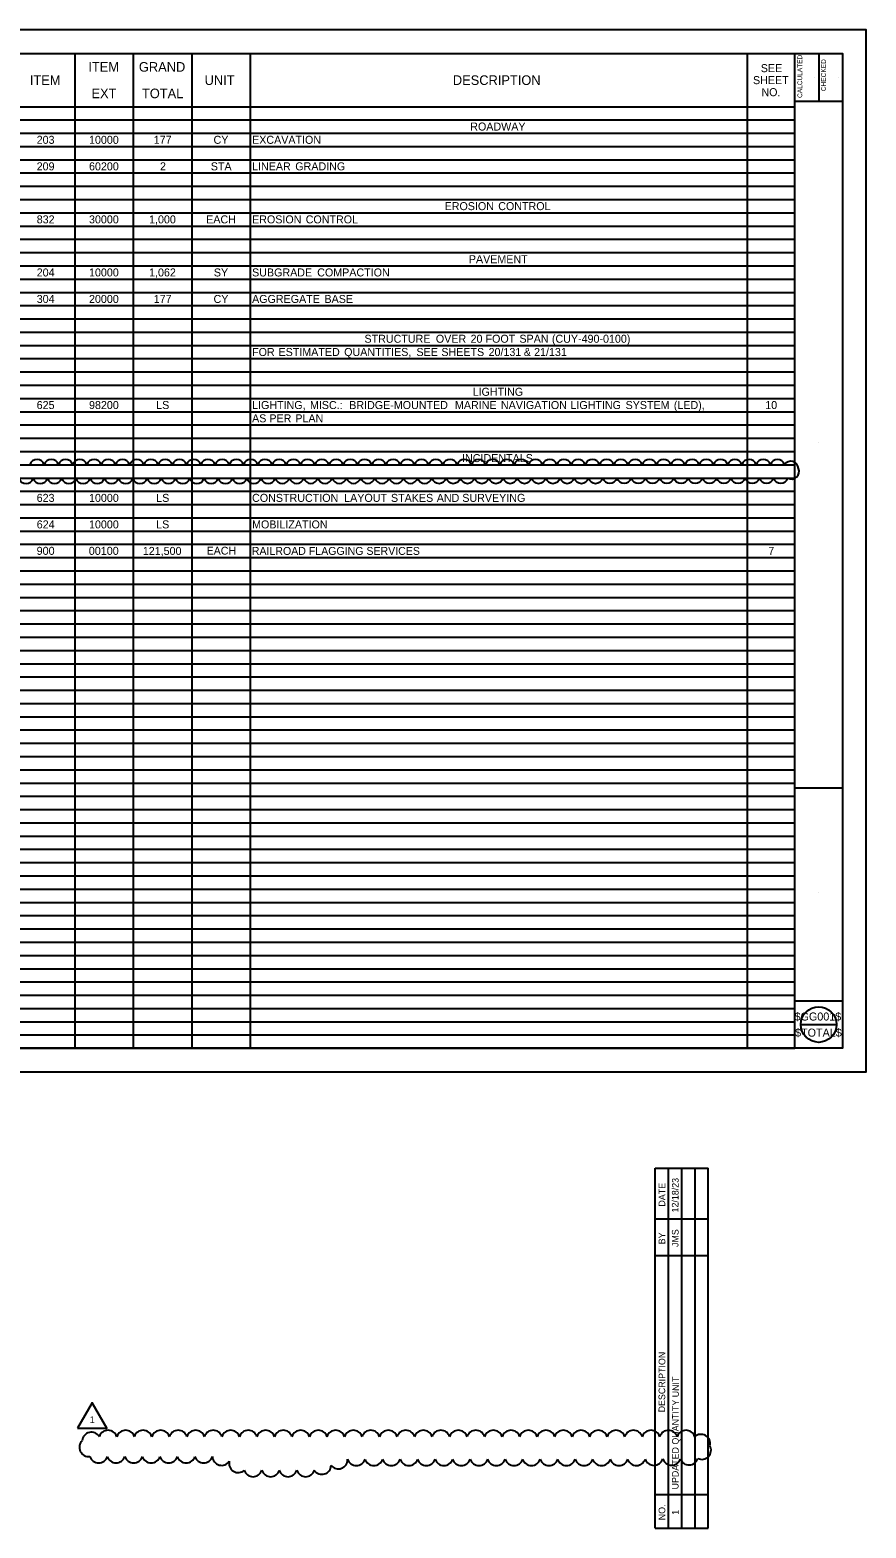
# Model space of a CAD drawing. Extents: x 0 to 34, y -9.6 to 22.
# Drawn here: x 16.35 to 34, y -9.63 to 22 of the extents above; entities that cross this region are included whole.
import ezdxf

# ---------------------------------------------------------------- set-up
doc = ezdxf.new("R2010")
doc.units = 0
for name, color, linetype in [('Default', 7, 'Continuous'), ('MU_Markup_Cloud', 7, 'Continuous'), ('MU_Markup_Text', 7, 'Continuous'), ('SH_Border', 7, 'Continuous'), ('SH_Cut_Line', 7, 'Continuous'), ('SH_Data', 7, 'Continuous'), ('SH_Text', 7, 'Continuous')]:
    doc.layers.add(name, color=color, linetype=linetype)

msp = doc.modelspace()

# ---------------------------------------------------------------- linework, layer by layer
at = {"layer": 'Default'}
for p, q in [((15.06, 21.5), (17.299, 21.5)), ((17.299, 21.5), (19.77, 21.5)), ((17.299, 0.5), (17.299, 21.5)), ((18.535, 0.5), (18.535, 21.5)), ((19.77, 21.5), (21.005, 21.5)), ((19.77, 0.5), (19.77, 21.5)), ((21.005, 21.5), (31.495, 21.5)), ((21.005, 0.5), (21.005, 21.5)), ((31.495, 21.5), (32.5, 21.5)), ((31.495, 0.5), (31.495, 21.5)), ((32.5, 0.5), (32.5, 21.5)), ((14.055, 20.38), (32.5, 20.38)), ((19.77, 20.38), (32.5, 20.38)), ((2, 20.1), (32.5, 20.1)), ((2, 19.82), (32.5, 19.82)), ((2, 19.54), (32.5, 19.54)), ((2, 19.26), (32.5, 19.26)), ((2, 18.98), (32.5, 18.98)), ((2, 18.7), (32.5, 18.7)), ((2, 18.42), (32.5, 18.42)), ((2, 18.14), (32.5, 18.14)), ((2, 17.86), (32.5, 17.86)), ((2, 17.58), (32.5, 17.58)), ((2, 17.3), (32.5, 17.3)), ((2, 17.02), (32.5, 17.02)), ((2, 16.74), (32.5, 16.74)), ((2, 16.46), (32.5, 16.46)), ((2, 16.18), (32.5, 16.18)), ((2, 15.9), (32.5, 15.9)), ((2, 15.62), (32.5, 15.62)), ((2, 15.34), (32.5, 15.34)), ((2, 15.06), (32.5, 15.06)), ((2, 14.78), (32.5, 14.78)), ((2, 14.5), (32.5, 14.5)), ((2, 14.22), (32.5, 14.22)), ((2, 13.94), (32.5, 13.94)), ((2, 13.66), (32.5, 13.66)), ((2, 13.38), (32.5, 13.38)), ((2, 13.1), (32.5, 13.1)), ((2, 12.82), (32.5, 12.82)), ((2, 12.54), (32.5, 12.54)), ((2, 12.26), (32.5, 12.26)), ((2, 11.98), (32.5, 11.98)), ((2, 11.7), (32.5, 11.7)), ((2, 11.42), (32.5, 11.42)), ((2, 11.14), (32.5, 11.14)), ((2, 10.86), (32.5, 10.86)), ((2, 10.58), (32.5, 10.58)), ((2, 10.3), (32.5, 10.3)), ((2, 10.02), (32.5, 10.02)), ((2, 9.74), (32.5, 9.74)), ((2, 9.46), (32.5, 9.46)), ((2, 9.18), (32.5, 9.18)), ((2, 8.9), (32.5, 8.9)), ((2, 8.62), (32.5, 8.62)), ((2, 8.34), (32.5, 8.34)), ((2, 8.06), (32.5, 8.06)), ((2, 7.78), (32.5, 7.78)), ((2, 7.5), (32.5, 7.5)), ((2, 7.22), (32.5, 7.22)), ((2, 6.94), (32.5, 6.94)), ((2, 6.66), (32.5, 6.66)), ((2, 6.38), (32.5, 6.38)), ((2, 6.1), (32.5, 6.1)), ((2, 5.82), (32.5, 5.82)), ((2, 5.54), (32.5, 5.54)), ((2, 5.26), (32.5, 5.26)), ((2, 4.98), (32.5, 4.98)), ((2, 4.7), (32.5, 4.7)), ((2, 4.42), (32.5, 4.42)), ((2, 4.14), (32.5, 4.14)), ((2, 3.86), (32.5, 3.86)), ((2, 3.58), (32.5, 3.58)), ((2, 3.3), (32.5, 3.3)), ((2, 3.02), (32.5, 3.02)), ((2, 2.74), (32.5, 2.74)), ((2, 2.46), (32.5, 2.46)), ((2, 2.18), (32.5, 2.18)), ((2, 1.9), (32.5, 1.9)), ((2, 1.62), (32.5, 1.62)), ((2, 1.34), (32.5, 1.34)), ((2, 1.06), (32.5, 1.06)), ((2, 0.78), (32.5, 0.78)), ((2, 0.5), (32.5, 0.5))]:
    msp.add_line(p, q, dxfattribs=at)
at = {"layer": 'MU_Markup_Cloud'}
msp.add_lwpolyline([(17.351, -7.521), (17.97, -7.521), (17.661, -6.985)], close=True, dxfattribs=at)
for centre, radius, start, end in [((16.498, 12.773), 0.158, 17.5, 162.5), ((16.799, 12.773), 0.158, 17.5, 162.5), ((17.1, 12.773), 0.158, 17.5, 162.5), ((17.4, 12.773), 0.158, 17.5, 162.5), ((17.701, 12.773), 0.158, 17.5, 162.5), ((18.002, 12.773), 0.158, 17.5, 162.5), ((18.302, 12.773), 0.158, 17.5, 162.5), ((18.603, 12.773), 0.158, 17.5, 162.5), ((18.903, 12.773), 0.158, 17.5, 162.5), ((19.204, 12.773), 0.158, 17.5, 162.5), ((19.505, 12.773), 0.158, 17.5, 162.5), ((19.805, 12.773), 0.158, 17.5, 162.5), ((20.106, 12.773), 0.158, 17.5, 162.5), ((20.407, 12.773), 0.158, 17.5, 162.5), ((20.707, 12.773), 0.158, 17.5, 162.5), ((21.008, 12.773), 0.158, 17.5, 162.5), ((21.309, 12.773), 0.158, 17.5, 162.5), ((21.609, 12.773), 0.158, 17.5, 162.5), ((21.91, 12.773), 0.158, 17.5, 162.5), ((22.21, 12.773), 0.158, 17.5, 162.5), ((22.511, 12.773), 0.158, 17.5, 162.5), ((22.812, 12.773), 0.158, 17.5, 162.5), ((23.112, 12.773), 0.158, 17.5, 162.5), ((23.413, 12.773), 0.158, 17.5, 162.5), ((23.714, 12.773), 0.158, 17.5, 162.5), ((24.014, 12.773), 0.158, 17.5, 162.5), ((24.315, 12.773), 0.158, 17.5, 162.5), ((24.615, 12.773), 0.158, 17.5, 162.5), ((24.916, 12.773), 0.158, 17.5, 162.5), ((25.217, 12.773), 0.158, 17.5, 162.5), ((25.517, 12.773), 0.158, 17.5, 162.5), ((25.818, 12.773), 0.158, 17.5, 162.5), ((26.119, 12.773), 0.158, 17.5, 162.5), ((26.419, 12.773), 0.158, 17.5, 162.5), ((26.72, 12.773), 0.158, 17.5, 162.5), ((27.021, 12.773), 0.158, 17.5, 162.5), ((27.321, 12.773), 0.158, 17.5, 162.5), ((27.622, 12.773), 0.158, 17.5, 162.5), ((27.922, 12.773), 0.158, 17.5, 162.5), ((28.223, 12.773), 0.158, 17.5, 162.5), ((28.524, 12.773), 0.158, 17.5, 162.5), ((28.824, 12.773), 0.158, 17.5, 162.5), ((29.125, 12.773), 0.158, 17.5, 162.5), ((29.426, 12.773), 0.158, 17.5, 162.5), ((29.726, 12.773), 0.158, 17.5, 162.5), ((30.027, 12.773), 0.158, 17.5, 162.5), ((30.327, 12.773), 0.158, 17.5, 162.5), ((30.628, 12.773), 0.158, 17.5, 162.5), ((30.929, 12.773), 0.158, 17.5, 162.5), ((31.229, 12.773), 0.158, 17.5, 162.5), ((31.53, 12.773), 0.158, 17.5, 162.5), ((31.831, 12.773), 0.158, 17.5, 162.5), ((32.131, 12.773), 0.158, 17.5, 162.5), ((32.414, 12.735), 0.158, 2.1746, 147.1746), ((32.429, 12.674), 0.157, 239.8312, 24.8312), ((16.266, 12.582), 0.158, 197.5195, 342.5195), ((16.566, 12.582), 0.158, 197.5197, 342.5197), ((16.867, 12.582), 0.158, 197.5199, 342.5199), ((17.168, 12.582), 0.158, 197.5201, 342.5201), ((17.468, 12.582), 0.158, 197.5201, 342.5201), ((17.769, 12.582), 0.158, 197.52, 342.52), ((18.069, 12.582), 0.158, 197.5199, 342.5199), ((18.37, 12.582), 0.158, 197.5198, 342.5198), ((18.671, 12.583), 0.158, 197.5198, 342.5198), ((18.971, 12.583), 0.158, 197.5197, 342.5197), ((19.272, 12.583), 0.158, 197.5196, 342.5196), ((19.573, 12.583), 0.158, 197.5195, 342.5195), ((19.873, 12.583), 0.158, 197.5194, 342.5194), ((20.174, 12.583), 0.158, 197.5193, 342.5193), ((20.474, 12.583), 0.158, 197.5192, 342.5192), ((20.775, 12.583), 0.158, 197.519, 342.519), ((21.076, 12.583), 0.158, 197.5189, 342.5189), ((21.376, 12.583), 0.158, 197.5188, 342.5188), ((21.677, 12.584), 0.158, 197.5187, 342.5187), ((21.978, 12.584), 0.158, 197.5185, 342.5185), ((22.278, 12.584), 0.158, 197.5184, 342.5184), ((22.579, 12.584), 0.158, 197.5182, 342.5182), ((22.88, 12.584), 0.158, 197.5181, 342.5181), ((23.18, 12.584), 0.158, 197.5179, 342.5179), ((23.481, 12.584), 0.158, 197.5178, 342.5178), ((23.781, 12.584), 0.158, 197.5176, 342.5176), ((24.082, 12.584), 0.158, 197.5174, 342.5174), ((24.383, 12.584), 0.158, 197.5172, 342.5172), ((24.683, 12.584), 0.158, 197.517, 342.517), ((24.984, 12.585), 0.158, 197.5168, 342.5168), ((25.285, 12.585), 0.158, 197.5166, 342.5166), ((25.585, 12.585), 0.158, 197.5163, 342.5163), ((25.886, 12.585), 0.158, 197.516, 342.516), ((26.186, 12.585), 0.158, 197.5158, 342.5158), ((26.487, 12.585), 0.158, 197.5155, 342.5155), ((26.788, 12.585), 0.158, 197.5151, 342.5151), ((27.088, 12.585), 0.158, 197.5148, 342.5148), ((27.389, 12.585), 0.158, 197.5144, 342.5144), ((27.69, 12.585), 0.158, 197.514, 342.514), ((27.99, 12.585), 0.158, 197.5135, 342.5135), ((28.291, 12.585), 0.158, 197.513, 342.513), ((28.592, 12.586), 0.158, 197.5124, 342.5124), ((28.892, 12.586), 0.158, 197.5118, 342.5118), ((29.193, 12.586), 0.158, 197.5111, 342.5111), ((29.493, 12.586), 0.158, 197.5102, 342.5102), ((29.794, 12.586), 0.158, 197.5093, 342.5093), ((30.095, 12.586), 0.158, 197.5081, 342.5081), ((30.395, 12.586), 0.158, 197.5067, 342.5067), ((30.696, 12.586), 0.158, 197.505, 342.505), ((30.997, 12.586), 0.158, 197.5028, 342.5028), ((31.297, 12.586), 0.158, 197.4998, 342.4998), ((31.598, 12.586), 0.158, 197.4955, 342.4955), ((31.898, 12.586), 0.158, 197.488, 342.488), ((32.199, 12.586), 0.158, 197.4703, 342.4703), ((17.998, -7.76), 0.194, 17.5, 162.5), ((18.367, -7.76), 0.194, 17.5, 162.5), ((18.737, -7.76), 0.194, 17.5, 162.5), ((19.107, -7.76), 0.194, 17.5, 162.5), ((19.477, -7.76), 0.194, 17.5, 162.5), ((19.846, -7.76), 0.194, 17.5, 162.5), ((20.216, -7.76), 0.194, 17.5, 162.5), ((20.586, -7.76), 0.194, 17.5, 162.5), ((20.956, -7.76), 0.194, 17.5, 162.5), ((21.325, -7.76), 0.194, 17.5, 162.5), ((21.695, -7.76), 0.194, 17.5, 162.5), ((22.065, -7.76), 0.194, 17.5, 162.5), ((22.435, -7.76), 0.194, 17.5, 162.5), ((22.804, -7.76), 0.194, 17.5, 162.5), ((23.174, -7.76), 0.194, 17.5, 162.5), ((23.544, -7.76), 0.194, 17.5, 162.5), ((23.914, -7.76), 0.194, 17.5, 162.5), ((24.283, -7.76), 0.194, 17.5, 162.5), ((24.653, -7.76), 0.194, 17.5, 162.5), ((25.023, -7.76), 0.194, 17.5, 162.5), ((25.393, -7.76), 0.194, 17.5, 162.5), ((25.762, -7.76), 0.194, 17.5, 162.5), ((26.132, -7.76), 0.194, 17.5, 162.5), ((26.502, -7.76), 0.194, 17.5, 162.5), ((26.871, -7.76), 0.194, 17.5, 162.5), ((27.241, -7.76), 0.194, 17.5, 162.5), ((27.611, -7.76), 0.194, 17.5, 162.5), ((27.981, -7.76), 0.194, 17.5, 162.5), ((28.35, -7.76), 0.194, 17.5, 162.5), ((28.72, -7.76), 0.194, 17.5, 162.5), ((29.09, -7.76), 0.194, 17.5, 162.5), ((29.46, -7.76), 0.194, 17.5, 162.5), ((29.829, -7.76), 0.194, 17.5, 162.5), ((30.199, -7.76), 0.194, 17.5, 162.5), ((17.585, -7.927), 0.194, 133.161, 278.161), ((17.646, -7.8), 0.194, 30.5448, 175.5448), ((30.513, -7.846), 0.194, 346.6844, 131.6844), ((30.533, -7.986), 0.194, 244.2994, 29.2994), ((17.797, -8.06), 0.194, 197.5, 342.5), ((18.167, -8.06), 0.194, 197.5, 342.5), ((18.537, -8.06), 0.194, 197.5, 342.5), ((18.907, -8.06), 0.194, 197.5, 342.5), ((19.276, -8.06), 0.194, 197.5, 342.5), ((19.646, -8.06), 0.194, 197.5, 342.5), ((20.016, -8.06), 0.194, 197.5, 342.5), ((20.395, -8.113), 0.194, 181.5215, 326.5215), ((20.745, -8.265), 0.194, 166.5598, 311.5598), ((22.86, -8.187), 0.194, 217.8482, 2.8482), ((23.238, -8.119), 0.194, 197.5, 342.5), ((23.608, -8.119), 0.194, 197.5, 342.5), ((23.978, -8.119), 0.194, 197.5, 342.5), ((24.348, -8.119), 0.194, 197.5, 342.5), ((24.718, -8.119), 0.194, 197.5, 342.5), ((25.087, -8.119), 0.194, 197.5, 342.5), ((25.457, -8.119), 0.194, 197.5, 342.5), ((25.827, -8.119), 0.194, 197.5, 342.5), ((26.196, -8.119), 0.194, 197.5, 342.5), ((26.566, -8.119), 0.194, 197.5, 342.5), ((26.936, -8.119), 0.194, 197.509, 342.509), ((27.306, -8.119), 0.194, 197.5309, 342.5309), ((27.675, -8.119), 0.194, 197.557, 342.557), ((28.045, -8.118), 0.194, 197.5885, 342.5885), ((28.415, -8.118), 0.194, 197.6278, 342.6278), ((28.784, -8.117), 0.194, 197.6786, 342.6786), ((29.154, -8.115), 0.194, 197.7481, 342.7481), ((29.524, -8.113), 0.194, 197.8514, 342.8514), ((29.893, -8.11), 0.194, 198.0307, 343.0307), ((30.263, -8.105), 0.194, 198.4927, 343.4927), ((21.058, -8.352), 0.194, 197.5, 342.5), ((21.428, -8.352), 0.194, 197.5, 342.5), ((21.798, -8.352), 0.194, 197.5, 342.5), ((22.167, -8.352), 0.194, 197.5, 342.5), ((22.513, -8.302), 0.194, 213.8846, 358.8846)]:
    msp.add_arc(centre, radius, start, end, dxfattribs=at)
at = {"layer": 'MU_Markup_Text'}
for p, q in [((29.549, -9.63), (29.549, -2.03)), ((29.549, -2.03), (30.669, -2.03)), ((29.829, -9.63), (29.829, -2.03)), ((30.109, -9.63), (30.109, -2.03)), ((30.389, -9.63), (30.389, -2.03)), ((30.669, -9.63), (30.669, -2.03)), ((29.549, -3.105), (30.669, -3.105)), ((29.549, -3.878), (30.669, -3.878)), ((29.549, -8.924), (30.669, -8.924)), ((29.549, -9.63), (30.669, -9.63))]:
    msp.add_line(p, q, dxfattribs=at)
at = {"layer": 'SH_Border'}
for p, q in [((32.5, 0.5), (32.5, 21.5)), ((33, 21.5), (33, 20.5)), ((32.5, 20.5), (33.5, 20.5)), ((32.5, 6), (33.5, 6)), ((32.5, 1.5), (33.5, 1.5))]:
    msp.add_line(p, q, dxfattribs=at)
msp.add_lwpolyline([(2, 21.5), (33.5, 21.5), (33.5, 0.5), (2, 0.5)], close=True, dxfattribs=at)
at = {"layer": 'SH_Cut_Line'}
msp.add_lwpolyline([(0, 0), (34, 0), (34, 22), (0, 22)], close=True, dxfattribs=at)
at = {"layer": 'SH_Data'}
for p, q in [((32.92, 21.004), (32.92, 21.004)), ((33.42, 21.004), (33.42, 21.004)), ((33, 13.292), (33, 13.292)), ((33, 3.792), (33, 3.792)), ((32.625, 1), (33.375, 1)), ((33, 1.085), (33, 1.085)), ((33, 0.745), (33, 0.745))]:
    msp.add_line(p, q, dxfattribs=at)
msp.add_circle((33, 1), 0.375, dxfattribs=at)

# ---------------------------------------------------------------- texts
at = {"layer": 'Default'}
for s, height, p in [('ITEM', 0.2027, (17.581, 21.119)), ('GRAND', 0.2027, (18.648, 21.119)), ('SEE', 0.1689, (31.778, 21.109)), ('ITEM', 0.2027, (16.345, 20.839)), ('UNIT', 0.2027, (20.036, 20.839)), ('DESCRIPTION', 0.20271, (25.277, 20.839)), ('SHEET', 0.1689, (31.613, 20.856)), ('EXT', 0.2027, (17.647, 20.559)), ('TOTAL', 0.2027, (18.713, 20.559)), ('NO.', 0.1689, (31.791, 20.602)), ('ROADWAY', 0.1689, (25.644, 19.876)), ('203', 0.1689, (16.49, 19.596)), ('10000', 0.1689, (17.595, 19.596)), ('177', 0.1689, (18.961, 19.596)), ('CY', 0.1689, (20.224, 19.596)), ('EXCAVATION', 0.1689, (21.038, 19.596)), ('209', 0.1689, (16.49, 19.036)), ('60200', 0.1689, (17.595, 19.036)), ('2', 0.169, (19.093, 19.036)), ('STA', 0.1689, (20.166, 19.036)), ('LINEAR', 0.1689, (21.038, 19.036)), (' GRADING', 0.1689, (21.887, 19.036)), ('EROSION', 0.1689, (25.103, 18.196)), (' CONTROL', 0.1689, (26.172, 18.196)), ('832', 0.1689, (16.491, 17.916)), ('30000', 0.1689, (17.595, 17.916)), ('1,000', 0.1689, (18.863, 17.916)), ('EACH', 0.1689, (20.069, 17.916)), ('EROSION', 0.1689, (21.038, 17.916)), (' CONTROL', 0.1689, (22.107, 17.916)), ('PAVEMENT', 0.1689, (25.614, 17.076)), ('204', 0.1689, (16.491, 16.796)), ('10000', 0.1689, (17.595, 16.796)), ('1,062', 0.1689, (18.863, 16.796)), ('SY', 0.1689, (20.231, 16.796)), ('SUBGRADE', 0.1689, (21.038, 16.796)), (' COMPACTION', 0.16893, (22.35, 16.796)), ('304', 0.1689, (16.491, 16.236)), ('20000', 0.1689, (17.595, 16.236)), ('177', 0.1689, (18.961, 16.236)), ('CY', 0.1689, (20.224, 16.236)), ('AGGREGATE', 0.1689, (21.038, 16.236)), (' BASE', 0.1689, (22.503, 16.236)), ('STRUCTURE', 0.1689, (23.411, 15.396)), (' OVER', 0.1689, (24.855, 15.396)), (' 20', 0.1689, (25.588, 15.396)), (' FOOT', 0.1689, (25.904, 15.396)), (' SPAN', 0.1689, (26.62, 15.396)), (' (CUY-490-0100)', 0.16893, (27.305, 15.396)), ('FOR', 0.1689, (21.038, 15.116)), (' ESTIMATED', 0.1689, (21.533, 15.116)), (' QUANTITIES,', 0.16893, (22.919, 15.116)), (' SEE', 0.1689, (24.445, 15.116)), (' SHEETS', 0.1689, (24.971, 15.116)), (' 20/131', 0.1689, (25.968, 15.116)), (' &', 0.1689, (26.712, 15.116)), (' 21/131', 0.1689, (26.929, 15.116)), ('LIGHTING', 0.1689, (25.694, 14.276)), ('625', 0.1689, (16.49, 13.996)), ('98200', 0.1689, (17.595, 13.996)), ('LS', 0.1689, (19.014, 13.996)), ('LIGHTING,', 0.1689, (21.038, 13.996)), (' MISC.:', 0.1689, (22.197, 13.996)), ('  BRIDGE-MOUNTED', 0.16893, (22.963, 13.996)), (' MARINE', 0.1689, (25.258, 13.996)), (' NAVIGATION', 0.16893, (26.229, 13.996)), (' LIGHTING', 0.1689, (27.696, 13.996)), (' SYSTEM', 0.1689, (28.861, 13.996)), (' (LED),', 0.1689, (29.879, 13.996)), ('10', 0.1689, (31.872, 13.996)), ('AS', 0.1689, (21.038, 13.716)), (' PER', 0.1689, (21.34, 13.716)), (' PLAN', 0.1689, (21.888, 13.716)), ('INCIDENTALS', 0.16893, (25.471, 12.876)), ('623', 0.1689, (16.49, 12.036)), ('10000', 0.1689, (17.595, 12.036)), ('LS', 0.1689, (19.014, 12.036)), ('CONSTRUCTION', 0.16893, (21.038, 12.036)), (' LAYOUT', 0.1689, (22.92, 12.036)), (' STAKES', 0.1689, (23.907, 12.036)), (' AND', 0.1689, (24.874, 12.036)), (' SURVEYING', 0.1689, (25.413, 12.036)), ('624', 0.1689, (16.491, 11.476)), ('10000', 0.1689, (17.595, 11.476)), ('LS', 0.1689, (19.014, 11.476)), ('MOBILIZATION', 0.16893, (21.038, 11.476)), ('121,500', 0.1689, (18.731, 10.916)), ('EACH', 0.167, (20.079, 10.922)), ('RAILROAD FLAGGING SERVICES', 0.167, (21.032, 10.917)), ('7', 0.169, (31.937, 10.916))]:
    msp.add_text(s, height=height, dxfattribs=at).set_placement(p)
at = {"layer": 'MU_Markup_Cloud'}
msp.add_text('1', height=0.14, dxfattribs=at).set_placement((17.61, -7.412))
at = {"layer": 'MU_Markup_Text'}
for s, p in [('DATE', (29.76, -2.843)), ('12/18/23', (30.04, -2.967)), ('BY', (29.76, -3.64)), ('JMS', (30.04, -3.696)), ('DESCRIPTION', (29.758, -7.188)), ('UPDATED QUANTITY UNIT', (30.041, -8.815)), ('NO.', (29.76, -9.466)), ('1', (30.042, -9.35))]:
    msp.add_text(s, height=0.14, rotation=89.7853, dxfattribs=at).set_placement(p)
at = {"layer": 'SH_Data'}
for s, p in [('CALCULATED', (32.652, 20.565)), ('CHECKED', (33.152, 20.708))]:
    msp.add_text(s, height=0.1, rotation=90, dxfattribs=at).set_placement(p)
at = {"layer": 'SH_Text'}
for s, p in [('900', (16.489, 10.917)), ('00100', (17.59, 10.917)), ('$GG001$', (32.491, 1.085)), ('$TOTAL$', (32.502, 0.745))]:
    msp.add_text(s, height=0.17, dxfattribs=at).set_placement(p)

doc.saveas('drawing.dxf')
